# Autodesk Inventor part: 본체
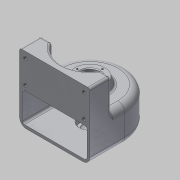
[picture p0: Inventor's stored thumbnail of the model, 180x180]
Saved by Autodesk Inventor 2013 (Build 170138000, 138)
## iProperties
Created: 2015-02
Part Number: 본체
Material: 알루미늄 6061
Document SubType Name: Modeling
Designer: Administrator
Density: 1 g/cm^3
Author: Administrator
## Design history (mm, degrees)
sketch "스케치1"
  geometry: L1 (-50, 0)-(-50, -50); L2 (-50, -50)-(50, -50); L3 (50, -50)-(50, 0); A1 r 50 centre (0, 0) between (50, 0) and (-50, 0); 1 further point
  constraints: 6 end point, 2 point on circle, 2 tangent, 1 centre point, 1 coincident, 1 parallel, 1 perpendicular, 1 vertical
  dimensions: "d0" = 100 diameter of A1; "d1" = 50 distance from line of L2 point (0, 0)
extrude "돌출1" new body sketch "스케치1" distance "d2" = 50; taper "d3" = 0 deg
sketch "스케치2"
  geometry: L1 (-50, 0)-(-50, -50) reference; L2 (-50, -50)-(50, -50) reference; L3 (50, -50)-(50, 0) reference; L4 (-34.641, -20)-(-50, -20); L5 (-50, -50)-(50, -50); L6 (50, -20)-(34.641, -20); L7 (50, -20)-(50, -50); L8 (-50, -20)-(-50, -50); A1 r 50 centre (0, 0) between (50, 0) and (-50, 0) reference; A2 r 40 centre (0, 0) between (-34.641, -20) and (34.641, -20); 2 further points
  constraints: 10 end point, 3 collinear, 2 midpoint, 2 point on circle, 2 point on line, 1 centre point, 1 coincident, 1 horizontal alignment, 1 parallel, 1 perpendicular
  dimensions: "d4" = 80 diameter of A2; "d5" = 30 distance of L6.start L2.end
extrude "돌출2" join sketch "스케치2" distance "d6" = 45; taper "d7" = 0 deg
sketch "스케치3"
  geometry: L1 (0, 60)-(0, -9); L2 (50, 0)-(50, 50) reference; L3 (0, 60)-(21.36, 60); L4 (21.36, 60)-(25, 50); L5 (25, 50)-(25, 0); L6 (25, 0)-(20, 0); L7 (20, 0)-(20, -9); L8 (20, -9)-(0, -9); L9 (50, 50)-(0, 50) reference; 2 further points
  constraints: 14 end point, 3 parallel, 2 perpendicular, 1 horizontal alignment, 1 midpoint, 1 vertical, 1 vertical alignment
  dimensions: "d8" = 69 distance of L1.start L1.end; "d10" = 110 deg angle of L9 L4; "d12" = 10 vertical distance of L3.end L4.end; "d13" = 9 distance of L6.end L7.end; "d14" = 50 diameter of L4.end L1; "d15" = 40 diameter of L7 L1
revolve "회전1" sketch "스케치3" stored, may be unused: angle "d16" = 90 deg
sketch "스케치4"
  geometry: L1 (0, 60)-(0, -9.561); L2 (-20, -9)-(20, -9) reference; L3 (-21.36, 60)-(21.36, 60) reference; L4 (0, 60)-(14, 60); L5 (14, 60)-(14, 50); L6 (14, 50)-(10, 50); L7 (10, 50)-(10, 46); L8 (10, 46)-(46, 46); L9 (46, 46)-(46, 4); L10 (46, 4)-(14, 4); L11 (14, 4)-(14, -4); L12 (14, -4)-(10, -4); L13 (10, -4)-(10, -6); L14 (10, -6)-(0, -6); L15 (0, 0)-(0, 0) reference; L16 (0, 0)-(0, 50) reference; L17 (0, 50)-(0, 50) reference; L18 (0, 0)-(0, 50) reference; L19 (50, 0)-(50, 50) reference; L20 (50, 50)-(0, 50) reference; L21 (0, 0)-(50, 0) reference; 2 further points
  constraints: 24 end point, 6 parallel, 3 perpendicular, 2 midpoint, 2 point on line, 1 collinear, 1 vertical, 1 vertical alignment
  dimensions: "d17" = 28 diameter of L5 L1; "d19" = 20 diameter of L7 L1; "d20" = 4 distance between parallel lines of L9 L19; "d21" = 4 distance between parallel lines of L8 L20; "d22" = 10 distance of L4.end L5.end; "d23" = 2 distance of L12.end L13.end; "d24" = 20 diameter of L13 L1; "d25" = 28 diameter of L11 L1; "d26" = 4 distance between parallel lines of L21 L10; "d27" = 8 distance of L10.end L11.end
revolve "회전2" sketch "스케치4" stored, may be unused: angle "d28" = 90 deg
sketch "스케치5"
  geometry: C1 r 14 at (0, 0) reference; 1 further point
  constraints: 1 vertical alignment
  dimensions: "d29" = 18 distance of C1.centre point (0, 18)
hole "구멍1" sketch "스케치5" at (0, 18) diameter "d30" = 2.459; stored, may be unused: countersink angle "d34" = 90 deg, drill point angle "d36" = 118 deg; dims "d31" = 6, "d32" = 4, "d33" = 2, "d35" = 9
sketch "스케치6"
  geometry: L1 (100, 0)-(0, 0) reference; L2 (0, 95)-(100, 95) reference; L3 (91.75, 86)-(8.25, 86); L4 (8.25, 86)-(8.25, 53); L5 (8.25, 53)-(91.75, 53); L6 (91.75, 53)-(91.75, 86); 7 further points
  constraints: 8 end point, 4 coincident, 2 midpoint, 2 parallel, 1 horizontal, 1 perpendicular, 1 vertical alignment
  dimensions: "d40" = 33 distance of L5.end L3.start; "d42" = 83.5 distance of L3.start L3.end; "d43" = 9 distance between parallel lines of L3 L2
hole "구멍2" sketch "스케치6" at (91.75, 86), (91.75, 53), (8.25, 86), (8.25, 53) diameter "d44" = 5.134; stored, may be unused: countersink angle "d48" = 90 deg, drill point angle "d50" = 118 deg; dims "d45" = 10, "d46" = 4, "d47" = 2, "d49" = 13
fillet "모깎기1" dims "d51" = 10
fillet "모깎기2" dims "d52" = 3
fillet "모깎기3" dims "d53" = 3
fillet "모깎기4" dims "d54" = 3
fillet "모깎기5" dims "d55" = 3
fillet "모깎기6" dims "d56" = 3
node "작업 평면1"
sketch "스케치7"
  geometry: 2 further points
  constraints: 1 vertical alignment, 1 other
  dimensions: "d57" = 25 distance of point (0, 0) point (0, 25)
feature "엠보싱1" sketch "스케치7" dims "d0" = 100, "d1" = 50, "d58" = 0.5, "d59" = 0
chamfer "모따기1" distance "d60" = 1; stored, may be unused: second distance "d61" = 2, angle "d62" = 45 deg
chamfer "모따기2" distance "d63" = 0.3; stored, may be unused: second distance "d64" = 2, angle "d65" = 45 deg
chamfer "모따기3" distance "d66" = 1; stored, may be unused: second distance "d67" = 2, angle "d68" = 45 deg; dims "d10" = 110 deg
fillet "모깎기7" dims "d69" = 0.3
fillet "모깎기8" dims "d70" = 3
sketch "스케치8"
  geometry: L1 (80, 0)-(0, 0) reference; L2 (86, 46)-(-6, 46); L3 (-6, 46)-(-6, 4); L4 (-6, 4)-(86, 4); L5 (86, 4)-(86, 46); 3 further points
  constraints: 8 end point, 2 midpoint, 2 parallel, 1 horizontal, 1 perpendicular, 1 vertical alignment
  dimensions: "d71" = 92 distance of L2.start L2.end; "d73" = 42 distance of L2.end L3.end; "d74" = 4 distance between parallel lines of L1 L4
extrude "돌출3" cut sketch "스케치8" distance "d75" = 50; taper "d76" = 0 deg
fillet "모깎기9" dims "d77" = 3
node "솔리드1"
pattern_circular "원형 패턴1" dims angle "d38" = 360 deg
node "투영된 루프1"
